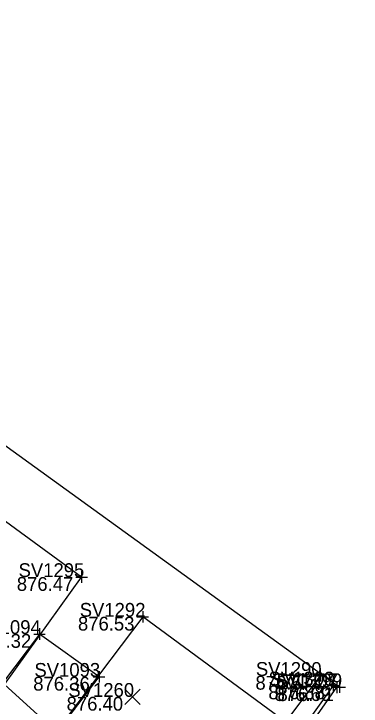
# Model space of a CAD drawing. Extents: x 1480001 to 1480402, y 379235 to 379603.
# Drawn here: x 1480278.2 to 1480308.4, y 379360.8 to 379421 of the extents above; entities that cross this region are included whole.
import ezdxf

# ---------------------------------------------------------------- set-up
doc = ezdxf.new("R2010")
doc.units = 0
for name, color, linetype in [('BD_X_Building', 7, 'Continuous'), ('PV_X_Curb', 7, 'Continuous'), ('PV_X_Driveway', 7, 'Continuous'), ('PV_X_Walk', 7, 'Continuous'), ('SV_X_Random_Point', 7, 'Continuous'), ('SV_X_Shot_Marker', 7, 'Continuous'), ('SV_X_Text_Elevation', 7, 'Continuous'), ('SV_X_Text_Name', 7, 'Continuous')]:
    doc.layers.add(name, color=color, linetype=linetype)

msp = doc.modelspace()

# ---------------------------------------------------------------- linework, layer by layer
at = {"layer": 'BD_X_Building'}
msp.add_line((1480271.911, 379387.504), (1480306.519, 379362.484), dxfattribs=at)
at = {"layer": 'PV_X_Curb'}
msp.add_lwpolyline([(1480305.96, 379362.631), (1480300.661, 379355.172), (1480299.212, 379353.42), (1480297.448, 379351.979), (1480295.46, 379350.738), (1480292.571, 379349.379)], dxfattribs=at)
at = {"layer": 'PV_X_Driveway'}
msp.add_lwpolyline([(1480292.11, 379348.712), (1480293.619, 379349.452), (1480297.028, 379351.282), (1480299.308, 379353.024), (1480300.735, 379354.566), (1480306.287, 379362.479)], dxfattribs=at)
at = {"layer": 'PV_X_Walk'}
for points in [[(1480355.123, 379297.828), (1480351.285, 379293.6), (1480334.098, 379309.328), (1480328.212, 379315.428), (1480328.737, 379316.329), (1480319.905, 379324.485), (1480307.606, 379335.13), (1480302.895, 379338.359), (1480281.823, 379358.406), (1480285.611, 379363.387), (1480280.441, 379367.109), (1480277.224, 379362.834), (1480260.819, 379378.019), (1480244.572, 379393.153), (1480235.613, 379401.335), (1480215.341, 379421.047)], [(1480304.825, 379363.469), (1480301.807, 379359.476), (1480289.404, 379368.611), (1480281.88, 379358.636), (1480277.384, 379362.714), (1480284.099, 379372.064), (1480266.845, 379384.676), (1480270.146, 379389.834)]]:
    msp.add_lwpolyline(points, dxfattribs=at)
at = {"layer": 'SV_X_Random_Point'}
for p, q in [((1480287.864, 379360.978), (1480289.198, 379362.313)), ((1480287.864, 379362.313), (1480289.198, 379360.978))]:
    msp.add_line(p, q, dxfattribs=at)
at = {"layer": 'SV_X_Shot_Marker'}
for p, q in [((1480283.599, 379372.064), (1480284.599, 379372.064)), ((1480284.099, 379372.564), (1480284.099, 379371.564)), ((1480284.099, 379372.064), (1480284.099, 379372.064)), ((1480289.404, 379369.111), (1480289.404, 379368.111)), ((1480288.904, 379368.611), (1480289.904, 379368.611)), ((1480289.404, 379368.611), (1480289.404, 379368.611)), ((1480280.441, 379367.609), (1480280.441, 379366.609)), ((1480279.941, 379367.109), (1480280.941, 379367.109)), ((1480280.441, 379367.109), (1480280.441, 379367.109)), ((1480285.611, 379363.887), (1480285.611, 379362.887)), ((1480304.825, 379363.969), (1480304.825, 379362.969)), ((1480285.111, 379363.387), (1480286.111, 379363.387)), ((1480285.611, 379363.387), (1480285.611, 379363.387)), ((1480304.325, 379363.469), (1480305.325, 379363.469)), ((1480304.825, 379363.469), (1480304.825, 379363.469)), ((1480305.96, 379363.131), (1480305.96, 379362.131)), ((1480306.519, 379362.984), (1480306.519, 379361.984)), ((1480305.46, 379362.631), (1480306.46, 379362.631)), ((1480305.787, 379362.479), (1480306.787, 379362.479)), ((1480305.96, 379362.631), (1480305.96, 379362.631)), ((1480306.019, 379362.484), (1480307.019, 379362.484)), ((1480306.287, 379362.979), (1480306.287, 379361.979)), ((1480306.287, 379362.479), (1480306.287, 379362.479)), ((1480306.519, 379362.484), (1480306.519, 379362.484))]:
    msp.add_line(p, q, dxfattribs=at)

# ---------------------------------------------------------------- texts
at = {"layer": 'SV_X_Text_Elevation'}
for s, p in [('876.47', (1480278.468, 379370.864)), ('876.53', (1480283.782, 379367.411)), ('876.32', (1480274.81, 379365.909)), ('876.36', (1480279.895, 379362.187)), ('876.57', (1480299.203, 379362.269)), ('876.88', (1480300.329, 379361.431)), ('876.69', (1480300.869, 379361.284)), ('876.71', (1480301.118, 379361.279)), ('876.40', (1480282.796, 379360.446))]:
    msp.add_text(s, height=1.2, dxfattribs=at).set_placement(p)
at = {"layer": 'SV_X_Text_Name'}
for s, p in [('SV1295', (1480278.62, 379372.064)), ('SV1292', (1480283.934, 379368.611)), ('SV1094', (1480274.839, 379367.109)), ('SV1093', (1480279.999, 379363.387)), ('SV1290', (1480299.242, 379363.469)), ('SV1308', (1480300.339, 379362.631)), ('SV1307', (1480300.675, 379362.479)), ('SV1299', (1480301.03, 379362.484)), ('SV1260', (1480282.948, 379361.646))]:
    msp.add_text(s, height=1.2, dxfattribs=at).set_placement(p)

doc.saveas('drawing.dxf')
